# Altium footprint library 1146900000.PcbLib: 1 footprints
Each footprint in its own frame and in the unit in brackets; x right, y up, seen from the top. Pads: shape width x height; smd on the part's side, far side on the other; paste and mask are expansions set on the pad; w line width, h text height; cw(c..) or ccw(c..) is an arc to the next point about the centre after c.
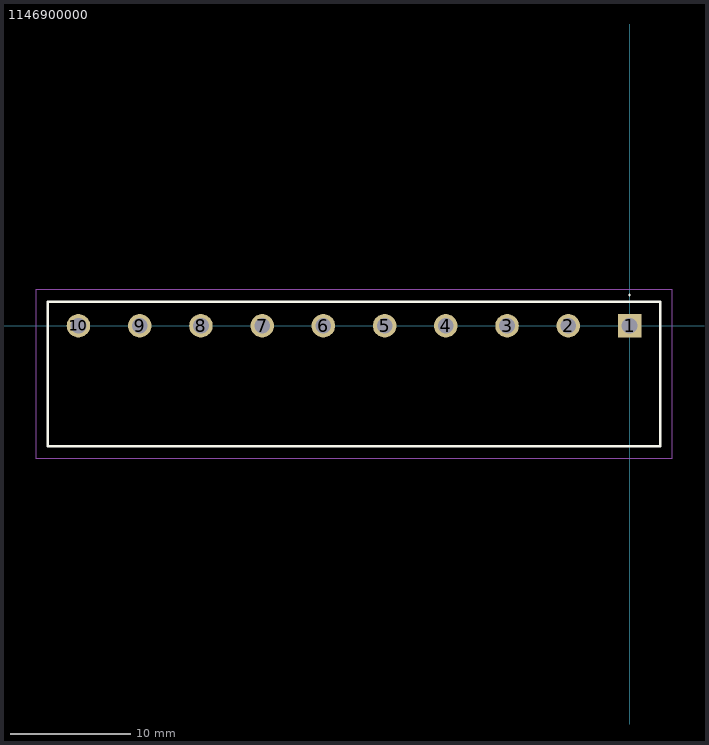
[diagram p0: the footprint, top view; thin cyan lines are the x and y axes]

## 1146900000 [mm]
pads (10):
  rect 1.95x1.95 hole 1.3: 1(0,0)
  round 1.95 hole 1.3: 2(-5.08,0) 3(-10.16,0) 4(-15.24,0) 5(-20.32,0) 6(-25.4,0) 7(-30.48,0) 8(-35.56,0) 9(-40.64,0) 10(-45.72,0)
Top Overlay:
  lines w0.1: 0,2.5 cw(c0,2.55) 0,2.6 ; 0,2.5 0,2.5 ; 0,2.5 ccw(c0,2.55) 0,2.6 ; 0,2.6 0,2.6
  lines w0.2: -48.26,-10 -48.26,2 2.54,2 2.54,-10 -48.26,-10
Mechanical 15:
  lines w0.1: -48.26,-10 -48.26,2 2.54,2 2.54,-10 -48.26,-10
Mechanical 20:
  lines w0.1: -49.26,-11 -49.26,3 3.54,3 3.54,-11 -49.26,-11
